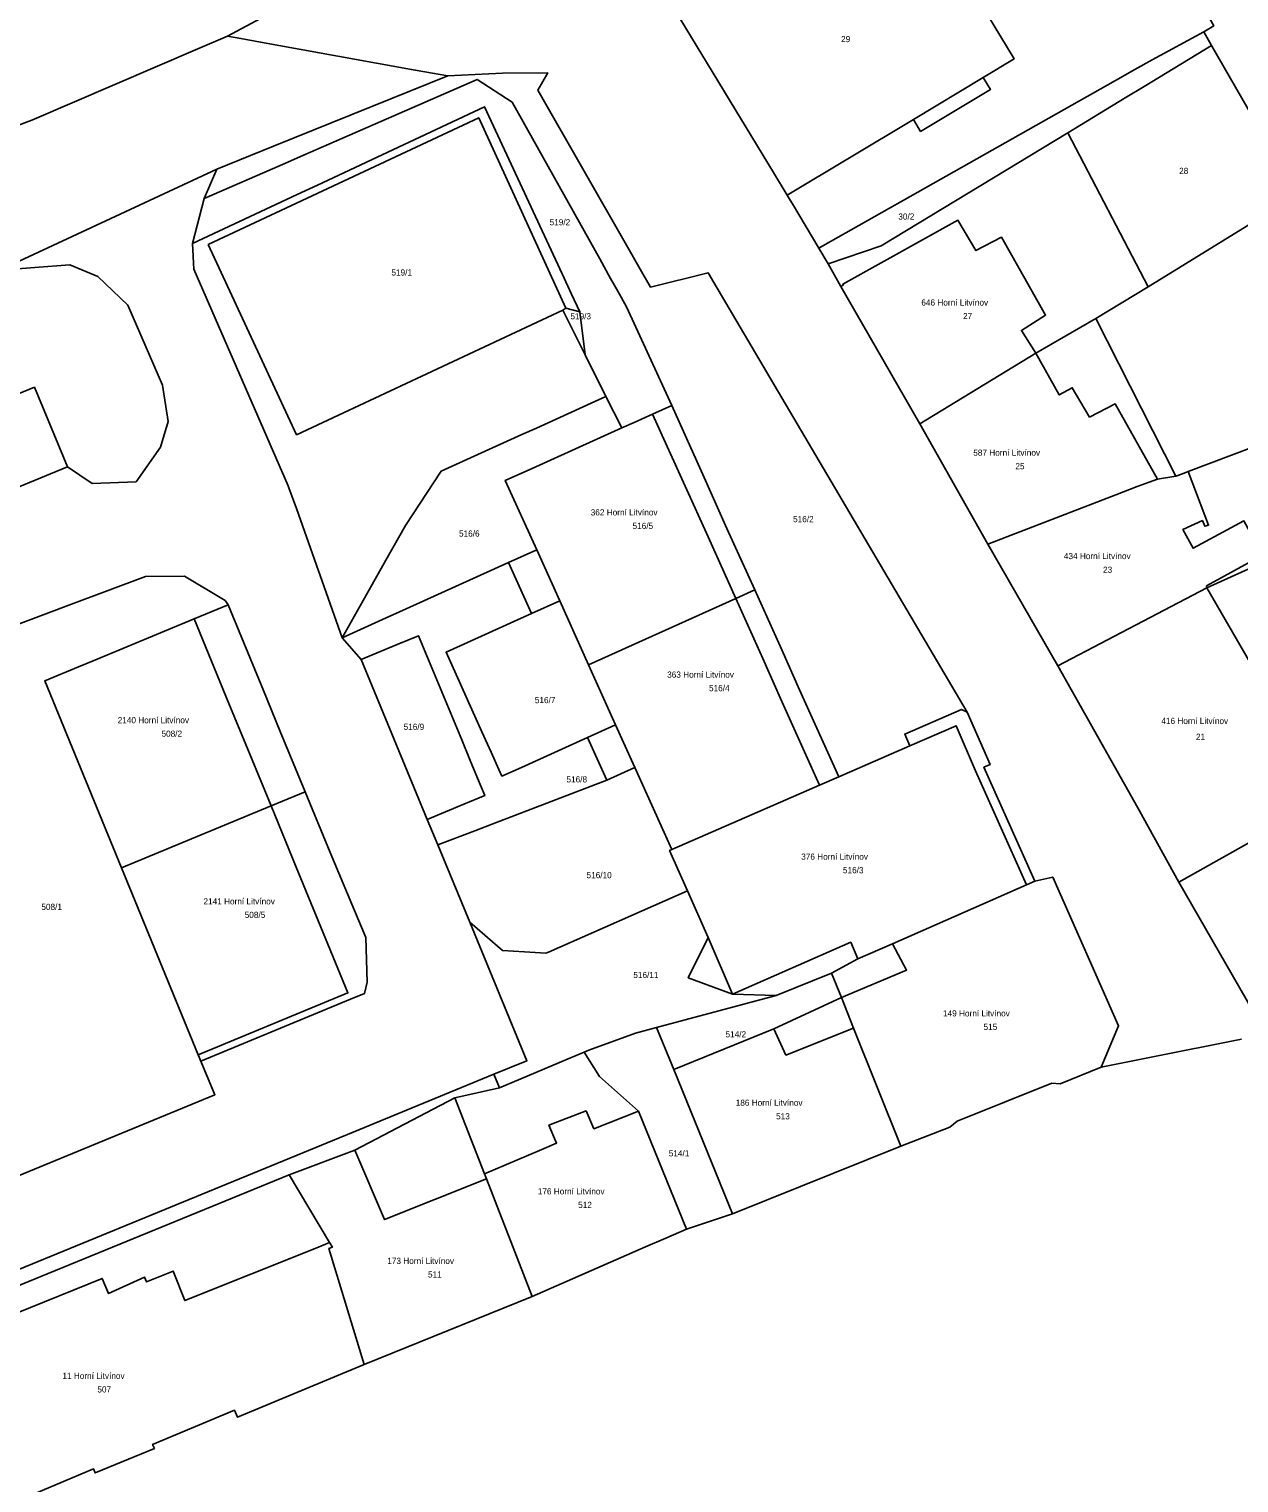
# Model space of a CAD drawing. Extents: x -792094 to -791524, y -979074 to -977761.
# Drawn here: x -791795.7 to -791697.5, y -978554.8 to -978436.7 of the extents above; entities that cross this region are included whole.
import ezdxf

# ---------------------------------------------------------------- set-up
doc = ezdxf.new("R2010")
doc.units = 0
doc.layers.add('katastr', color=7, linetype='Continuous')

msp = doc.modelspace()

# ---------------------------------------------------------------- linework, layer by layer
at = {"layer": 'katastr'}
for points in [[(-791639.24, -978372.34), (-791665.73, -978384.71), (-791679.28, -978391.82), (-791713.44, -978413.95), (-791712.96, -978414.79), (-791712, -978414.2), (-791699.5, -978436.46), (-791700.32, -978436.96), (-791699.69, -978438.07), (-791692.7, -978450.2), (-791683.8, -978465.99), (-791679.66, -978473.05), (-791670.22, -978489.33), (-791668.76, -978491.84), (-791668.28, -978492.67), (-791665.46, -978492.66), (-791655.51, -978492.64), (-791656.09, -978490.59), (-791634.23, -978485.99)], [(-791774.26, -978434.43), (-791779.62, -978437.31), (-791778.55, -978437.5), (-791776.94, -978437.79), (-791764.37, -978440.06), (-791761.73, -978440.54), (-791757.3, -978440.3), (-791753.61, -978440.27), (-791754.43, -978441.69), (-791747.1, -978454.48), (-791746.2, -978456.05), (-791745.26, -978457.69), (-791740.59, -978456.52), (-791740.13, -978457.31), (-791719.53, -978492.23), (-791717.68, -978496.48), (-791718.18, -978496.7), (-791714.04, -978505.95), (-791712.59, -978505.62), (-791707.23, -978517.71), (-791708.64, -978521.07), (-791704.72, -978520.29), (-791697.24, -978518.8)], [(-791695.21, -978518.4), (-791702.33, -978506.02), (-791705.66, -978500), (-791712.17, -978488.46), (-791717.87, -978478.58), (-791723.37, -978468.8), (-791729.8, -978457.63), (-791730.83, -978455.79), (-791731.58, -978454.53), (-791733.73, -978450.92), (-791733.91, -978450.62), (-791734.16, -978450.22), (-791735.27, -978448.37), (-791743.77, -978434.34)], [(-791798.15, -978456.32), (-791780.49, -978448.1), (-791775.89, -978446.25), (-791774.21, -978445.57), (-791761.73, -978440.54), (-791764.37, -978440.06), (-791776.94, -978437.79), (-791778.55, -978437.5), (-791779.62, -978437.31), (-791782.04, -978438.34), (-791795.52, -978444.13), (-791797.38, -978444.82)], [(-791819.57, -978546.91), (-791769.41, -978526.33), (-791757.99, -978521.62), (-791755.3, -978520.54), (-791759.94, -978509.29), (-791762.54, -978503.01), (-791763.4, -978500.93), (-791768.76, -978487.94), (-791770.31, -978486.17), (-791774.03, -978475.68), (-791774.64, -978473.99), (-791774.69, -978473.84), (-791782.37, -978456.24), (-791782.47, -978454.15), (-791781.53, -978450.5), (-791780.49, -978448.1), (-791798.15, -978456.32), (-791792.44, -978455.89), (-791790.15, -978456.83), (-791787.73, -978459.17), (-791784.9, -978465.65), (-791784.46, -978468.6), (-791785.07, -978470.7), (-791787.06, -978473.52), (-791790.63, -978473.64), (-791792.64, -978472.3), (-791843.49, -978493.26)], [(-791796.68, -978529.91), (-791780.67, -978523.32), (-791781.8, -978520.57), (-791782.01, -978520.06), (-791788.24, -978504.87), (-791794.47, -978489.67), (-791791.72, -978488.53), (-791790.53, -978488.04), (-791782.34, -978484.64), (-791779.57, -978483.49), (-791779.82, -978483.14), (-791783.13, -978481.18), (-791786.28, -978481.2), (-791792.51, -978483.54), (-791797.47, -978485.4)], [(-791797.47, -978485.4), (-791792.51, -978483.54), (-791786.28, -978481.2), (-791783.13, -978481.18), (-791779.82, -978483.14), (-791779.57, -978483.49), (-791776.71, -978490.45), (-791775.34, -978493.78), (-791773.32, -978498.69), (-791771.28, -978503.63), (-791769.89, -978506.97), (-791768.39, -978510.54), (-791768.28, -978514.16), (-791768.49, -978515.07), (-791769.63, -978515.54), (-791781.8, -978520.57), (-791780.67, -978523.32), (-791796.68, -978529.91)], [(-791697.24, -978518.8), (-791704.72, -978520.29), (-791708.64, -978521.07), (-791711.99, -978522.42), (-791712.65, -978522.37), (-791720.34, -978525.46), (-791720.94, -978525.94), (-791724.92, -978527.48), (-791738.59, -978532.97), (-791742.35, -978534.22), (-791744.02, -978534.95), (-791745.67, -978535.67), (-791754.88, -978539.7), (-791768.52, -978545.22), (-791778.82, -978549.5), (-791779.05, -978548.94), (-791785.71, -978551.71), (-791785.57, -978552.04), (-791790.37, -978554.03), (-791790.51, -978553.7), (-791797.13, -978556.47)], [(-791811.43, -978544.86), (-791774.63, -978529.81), (-791769.28, -978527.8), (-791761.16, -978523.56), (-791757.54, -978522.74), (-791757.99, -978521.62), (-791769.41, -978526.33), (-791819.57, -978546.91)], [(-791797.13, -978556.47), (-791790.51, -978553.7), (-791790.37, -978554.03), (-791785.57, -978552.04), (-791785.71, -978551.71), (-791779.05, -978548.94), (-791778.82, -978549.5), (-791768.52, -978545.22), (-791771.39, -978535.79), (-791771.11, -978535.68), (-791771.33, -978535.31), (-791772.36, -978535.73), (-791783.1, -978540.03), (-791784.04, -978537.63), (-791786.21, -978538.51), (-791786.37, -978538.11), (-791789.29, -978539.46), (-791789.81, -978538.22), (-791796.77, -978541.06)]]:
    msp.add_lwpolyline(points, dxfattribs=at)
for points in [[(-791800.48, -978414.05), (-791800.29, -978417.39), (-791800.13, -978420.23), (-791799.16, -978437.14), (-791798.94, -978441.72), (-791798.74, -978445.45), (-791797.38, -978444.82), (-791795.52, -978444.13), (-791782.04, -978438.34), (-791779.62, -978437.31), (-791774.26, -978434.43), (-791773.12, -978431.78), (-791776.62, -978427.28), (-791778.16, -978426.44), (-791786.66, -978421.71), (-791796.41, -978416.2), (-791798.26, -978415.26)], [(-791731.58, -978454.53), (-791731.27, -978454.35), (-791707.49, -978440.91), (-791705.92, -978440.02), (-791704.52, -978439.23), (-791700.32, -978436.96), (-791699.5, -978436.46), (-791712, -978414.2), (-791712.96, -978414.79), (-791717.16, -978417.4), (-791732.42, -978426.87), (-791744.02, -978433.92), (-791743.77, -978434.34), (-791725.3, -978423.3), (-791715.73, -978439.15), (-791718.24, -978440.67), (-791717.65, -978441.64), (-791723.32, -978445.04), (-791723.9, -978444.08), (-791734.16, -978450.22), (-791733.91, -978450.62), (-791733.73, -978450.92)], [(-791723.9, -978444.08), (-791718.24, -978440.67), (-791715.73, -978439.15), (-791725.3, -978423.3), (-791743.77, -978434.34), (-791735.27, -978448.37), (-791734.16, -978450.22)], [(-791715.73, -978439.15), (-791725.3, -978423.3), (-791743.77, -978434.34), (-791735.27, -978448.37), (-791734.16, -978450.22), (-791723.9, -978444.08), (-791723.32, -978445.04), (-791717.65, -978441.64), (-791718.24, -978440.67)], [(-791711.35, -978445.15), (-791706.69, -978442.32), (-791705.15, -978441.38), (-791699.69, -978438.07), (-791700.32, -978436.96), (-791704.52, -978439.23), (-791705.92, -978440.02), (-791707.49, -978440.91), (-791731.27, -978454.35), (-791731.58, -978454.53), (-791730.83, -978455.79), (-791726.52, -978454.35)], [(-791704.84, -978457.66), (-791692.7, -978450.2), (-791699.69, -978438.07), (-791705.15, -978441.38), (-791706.69, -978442.32), (-791711.35, -978445.15)], [(-791751, -978459.7), (-791750.57, -978463.19), (-791748.88, -978466.58), (-791747.6, -978469.13), (-791746.6, -978468.68), (-791745.09, -978468), (-791743.54, -978467.3), (-791747.21, -978459.28), (-791747.91, -978458.03), (-791748.5, -978456.98), (-791749.38, -978455.39), (-791756.49, -978442.66), (-791759.34, -978440.82), (-791773.51, -978447), (-791775.16, -978447.72), (-791781.53, -978450.5), (-791782.47, -978454.15), (-791773.96, -978450.17), (-791772.33, -978449.4), (-791758.74, -978443.04), (-791752.43, -978456.62), (-791751.67, -978458.26)], [(-791754.43, -978441.69), (-791753.61, -978440.27), (-791757.3, -978440.3), (-791761.73, -978440.54), (-791774.21, -978445.57), (-791775.89, -978446.25), (-791780.49, -978448.1), (-791781.53, -978450.5), (-791775.16, -978447.72), (-791773.51, -978447), (-791759.34, -978440.82), (-791756.49, -978442.66), (-791749.38, -978455.39), (-791748.5, -978456.98), (-791747.91, -978458.03), (-791747.21, -978459.28), (-791743.54, -978467.3), (-791740.91, -978473.16), (-791739.05, -978477.3), (-791736.78, -978482.29), (-791734.6, -978487.17), (-791733.15, -978490.4), (-791729.96, -978497.47), (-791724.19, -978494.96), (-791724.61, -978494), (-791719.99, -978492), (-791719.53, -978492.23), (-791740.13, -978457.31), (-791740.59, -978456.52), (-791745.26, -978457.69), (-791746.2, -978456.05), (-791747.1, -978454.48)], [(-791782.47, -978454.15), (-791782.37, -978456.24), (-791774.69, -978473.84), (-791774.64, -978473.99), (-791774.03, -978475.68), (-791770.31, -978486.17), (-791767.88, -978481.86), (-791766.76, -978479.87), (-791765.17, -978477.06), (-791762.28, -978472.64), (-791755.71, -978469.67), (-791754.53, -978469.14), (-791750.09, -978467.13), (-791748.88, -978466.58), (-791750.57, -978463.19), (-791752.39, -978459.56), (-791752.14, -978459.41), (-791751, -978459.7), (-791751.67, -978458.26), (-791752.43, -978456.62), (-791758.74, -978443.04), (-791772.33, -978449.4), (-791773.96, -978450.17)], [(-791781.21, -978454.23), (-791774.01, -978469.68), (-791752.39, -978459.56), (-791752.14, -978459.41), (-791759.21, -978443.93)], [(-791704.84, -978457.66), (-791711.35, -978445.15), (-791726.52, -978454.35), (-791730.83, -978455.79), (-791729.8, -978457.63), (-791723.37, -978468.8), (-791713.97, -978463.05), (-791709.08, -978460.25)], [(-791692.67, -978469.32), (-791683.8, -978465.99), (-791692.7, -978450.2), (-791704.84, -978457.66), (-791709.08, -978460.25), (-791702.58, -978473.05), (-791702.04, -978472.85), (-791701.59, -978472.66)], [(-791729.8, -978457.63), (-791723.37, -978468.8), (-791713.97, -978463.05), (-791715.13, -978461.21), (-791713.16, -978459.96), (-791716.76, -978453.62), (-791718.82, -978454.72), (-791720.29, -978452.26), (-791729.63, -978457.45), (-791729.6, -978457.53)], [(-791852.16, -978500.54), (-791841.16, -978498.91), (-791843.49, -978493.26), (-791846.16, -978486.79), (-791795.31, -978465.83), (-791792.64, -978472.3), (-791790.63, -978473.64), (-791787.06, -978473.52), (-791785.07, -978470.7), (-791784.46, -978468.6), (-791784.9, -978465.65), (-791787.73, -978459.17), (-791790.15, -978456.83), (-791792.44, -978455.89), (-791798.15, -978456.32), (-791799.08, -978456.73), (-791857.93, -978482.79), (-791858.41, -978481.73), (-791859.55, -978479.21), (-791861.86, -978480.18)], [(-791750.57, -978463.19), (-791751, -978459.7), (-791752.14, -978459.41), (-791752.39, -978459.56)], [(-791723.37, -978468.8), (-791717.87, -978478.58), (-791707.45, -978474.56), (-791705.72, -978473.89), (-791704.08, -978473.28), (-791702.58, -978473.05), (-791709.08, -978460.25), (-791713.97, -978463.05)], [(-791723.37, -978468.8), (-791717.87, -978478.58), (-791707.45, -978474.56), (-791705.72, -978473.89), (-791704.08, -978473.28), (-791707.51, -978467.18), (-791709.59, -978468.25), (-791711, -978465.86), (-791712.06, -978466.45), (-791713.97, -978463.05)], [(-791756.79, -978480.06), (-791754.51, -978479.04), (-791757.06, -978473.4), (-791754.57, -978472.28), (-791753.39, -978471.74), (-791747.6, -978469.13), (-791748.88, -978466.58), (-791750.09, -978467.13), (-791754.53, -978469.14), (-791755.71, -978469.67), (-791762.28, -978472.64), (-791765.17, -978477.06), (-791766.76, -978479.87), (-791767.88, -978481.86), (-791770.31, -978486.17), (-791766.75, -978484.56), (-791765.11, -978483.82)], [(-791754.92, -978484.21), (-791752.64, -978483.18), (-791750.29, -978488.39), (-791738.33, -978482.99), (-791736.78, -978482.29), (-791739.05, -978477.3), (-791740.91, -978473.16), (-791743.54, -978467.3), (-791745.09, -978468), (-791746.6, -978468.68), (-791747.6, -978469.13), (-791753.39, -978471.74), (-791754.57, -978472.28), (-791757.06, -978473.4), (-791754.51, -978479.04), (-791756.79, -978480.06)], [(-791745.09, -978468), (-791746.6, -978468.68), (-791747.6, -978469.13), (-791753.39, -978471.74), (-791754.57, -978472.28), (-791757.06, -978473.4), (-791754.51, -978479.04), (-791752.64, -978483.18), (-791750.29, -978488.39), (-791738.33, -978482.99), (-791740.59, -978477.99), (-791742.46, -978473.85)], [(-791704.08, -978473.28), (-791705.72, -978473.89), (-791707.45, -978474.56), (-791717.87, -978478.58), (-791712.17, -978488.46), (-791700.06, -978482.13), (-791690.47, -978477.8), (-791689.99, -978477.58), (-791688.64, -978476.97), (-791690.81, -978473.51), (-791691.65, -978472.15), (-791692.67, -978469.32), (-791701.59, -978472.66), (-791702.04, -978472.85), (-791702.58, -978473.05)], [(-791717.87, -978478.58), (-791712.17, -978488.46), (-791700.06, -978482.13), (-791700.1, -978481.97), (-791695.54, -978479.47), (-791697.06, -978476.68), (-791701.18, -978478.9), (-791702.01, -978477.39), (-791700.43, -978476.66), (-791700.22, -978477.12), (-791699.93, -978477.04), (-791701.59, -978472.66), (-791702.04, -978472.85), (-791702.58, -978473.05), (-791704.08, -978473.28), (-791705.72, -978473.89), (-791707.45, -978474.56)], [(-791705.66, -978500), (-791702.33, -978506.02), (-791691.58, -978500), (-791689.96, -978499.12), (-791683.28, -978495.52), (-791683.09, -978495.42), (-791680.78, -978494.33), (-791690.47, -978477.8), (-791700.06, -978482.13), (-791712.17, -978488.46)], [(-791770.31, -978486.17), (-791768.76, -978487.94), (-791765.84, -978486.73), (-791764.1, -978486.01), (-791760.6, -978494.48), (-791759.91, -978496.15), (-791759.31, -978497.59), (-791758.73, -978499), (-791760.42, -978499.7), (-791763.4, -978500.93), (-791762.54, -978503.01), (-791759.53, -978501.86), (-791757.85, -978501.21), (-791748.81, -978497.75), (-791750.37, -978494.28), (-791755.75, -978496.71), (-791757.33, -978497.42), (-791757.58, -978496.87), (-791758.21, -978495.46), (-791758.96, -978493.81), (-791761.87, -978487.35), (-791754.92, -978484.21), (-791756.79, -978480.06), (-791765.11, -978483.82), (-791766.75, -978484.56)], [(-791736.78, -978482.29), (-791738.33, -978482.99), (-791750.29, -978488.39), (-791748.1, -978493.25), (-791750.37, -978494.28), (-791748.81, -978497.75), (-791746.53, -978496.71), (-791743.53, -978503.37), (-791731.52, -978498.15), (-791729.96, -978497.47), (-791733.15, -978490.4), (-791734.6, -978487.17)], [(-791712.17, -978488.46), (-791705.66, -978500), (-791702.33, -978506.02), (-791691.58, -978500), (-791689.96, -978499.12), (-791693.19, -978494.23), (-791692.11, -978493.64), (-791694.41, -978489.79), (-791695.3, -978490.34), (-791700.06, -978482.13)], [(-791773.32, -978498.69), (-791775.34, -978493.78), (-791776.71, -978490.45), (-791779.57, -978483.49), (-791782.34, -978484.64), (-791790.53, -978488.04), (-791791.72, -978488.53), (-791794.47, -978489.67), (-791788.24, -978504.87), (-791776.09, -978499.83)], [(-791750.37, -978494.28), (-791748.1, -978493.25), (-791750.29, -978488.39), (-791752.64, -978483.18), (-791754.92, -978484.21), (-791761.87, -978487.35), (-791758.96, -978493.81), (-791758.21, -978495.46), (-791757.58, -978496.87), (-791757.33, -978497.42), (-791755.75, -978496.71)], [(-791738.33, -978482.99), (-791750.29, -978488.39), (-791748.1, -978493.25), (-791746.53, -978496.71), (-791743.53, -978503.37), (-791731.52, -978498.15), (-791734.69, -978491.1), (-791736.15, -978487.87)], [(-791778.14, -978494.86), (-791779.52, -978491.51), (-791782.34, -978484.64), (-791790.53, -978488.04), (-791791.72, -978488.53), (-791794.47, -978489.67), (-791788.24, -978504.87), (-791776.09, -978499.83)], [(-791763.4, -978500.93), (-791760.42, -978499.7), (-791758.73, -978499), (-791759.31, -978497.59), (-791759.91, -978496.15), (-791760.6, -978494.48), (-791764.1, -978486.01), (-791765.84, -978486.73), (-791768.76, -978487.94)], [(-791731.52, -978498.15), (-791743.53, -978503.37), (-791743.71, -978503.45), (-791742.26, -978506.73), (-791740.59, -978510.52), (-791742.19, -978513.8), (-791738.61, -978515.12), (-791735.05, -978515.23), (-791730.55, -978513.43), (-791728.43, -978512.27), (-791725.61, -978511.04), (-791714.72, -978506.26), (-791714.04, -978505.95), (-791718.18, -978496.7), (-791717.68, -978496.48), (-791719.53, -978492.23), (-791719.99, -978492), (-791724.61, -978494), (-791724.19, -978494.96), (-791729.96, -978497.47)], [(-791740.59, -978510.52), (-791738.61, -978515.12), (-791729, -978510.92), (-791728.43, -978512.27), (-791725.61, -978511.04), (-791714.72, -978506.26), (-791718.87, -978497), (-791720.43, -978493.33), (-791724.19, -978494.96), (-791729.96, -978497.47), (-791731.52, -978498.15), (-791743.53, -978503.37), (-791743.71, -978503.45), (-791742.26, -978506.73)], [(-791695.21, -978518.4), (-791682.9, -978511.6), (-791676.17, -978508.15), (-791680.86, -978500), (-791683.28, -978495.52), (-791689.96, -978499.12), (-791691.58, -978500), (-791702.33, -978506.02)], [(-791759.94, -978509.29), (-791757.28, -978511.58), (-791755.5, -978511.7), (-791753.78, -978511.81), (-791753.55, -978511.71), (-791742.26, -978506.73), (-791743.71, -978503.45), (-791743.53, -978503.37), (-791746.53, -978496.71), (-791748.81, -978497.75), (-791757.85, -978501.21), (-791759.53, -978501.86), (-791762.54, -978503.01)], [(-791769.89, -978506.97), (-791771.28, -978503.63), (-791773.32, -978498.69), (-791776.09, -978499.83), (-791788.24, -978504.87), (-791782.01, -978520.06), (-791781.8, -978520.57), (-791769.63, -978515.54), (-791768.49, -978515.07), (-791768.28, -978514.16), (-791768.39, -978510.54)], [(-791782.01, -978520.06), (-791769.84, -978515.03), (-791772.66, -978508.18), (-791774.04, -978504.82), (-791776.09, -978499.83), (-791788.24, -978504.87)], [(-791702.33, -978506.02), (-791695.21, -978518.4), (-791682.9, -978511.6), (-791685.15, -978507.64), (-791683.48, -978506.74), (-791686.11, -978502.21), (-791688.06, -978503.2), (-791689.96, -978499.12), (-791691.58, -978500)], [(-791725.61, -978511.04), (-791728.43, -978512.27), (-791730.55, -978513.43), (-791729.74, -978515.4), (-791728.77, -978517.88), (-791724.92, -978527.48), (-791720.94, -978525.94), (-791720.34, -978525.46), (-791712.65, -978522.37), (-791711.99, -978522.42), (-791708.64, -978521.07), (-791707.23, -978517.71), (-791712.59, -978505.62), (-791714.04, -978505.95), (-791714.72, -978506.26)], [(-791728.77, -978517.88), (-791724.92, -978527.48), (-791720.94, -978525.94), (-791720.34, -978525.46), (-791712.65, -978522.37), (-791711.99, -978522.42), (-791708.64, -978521.07), (-791707.23, -978517.71), (-791712.59, -978505.62), (-791714.04, -978505.95), (-791714.72, -978506.26), (-791725.61, -978511.04), (-791724.46, -978513.18), (-791729.74, -978515.4)], [(-791744.78, -978517.83), (-791735.05, -978515.23), (-791738.61, -978515.12), (-791742.19, -978513.8), (-791740.59, -978510.52), (-791742.26, -978506.73), (-791753.55, -978511.71), (-791753.78, -978511.81), (-791755.5, -978511.7), (-791757.28, -978511.58), (-791759.94, -978509.29), (-791755.3, -978520.54), (-791757.99, -978521.62), (-791757.54, -978522.74), (-791756.49, -978522.3), (-791751.94, -978520.38), (-791750.64, -978519.83), (-791750.27, -978519.69), (-791746.49, -978518.29)], [(-791730.55, -978513.43), (-791735.05, -978515.23), (-791744.78, -978517.83), (-791743.38, -978521.26), (-791735.23, -978517.95), (-791729.74, -978515.4)], [(-791728.77, -978517.88), (-791729.74, -978515.4), (-791735.23, -978517.95), (-791743.38, -978521.26), (-791738.59, -978532.97), (-791724.92, -978527.48)], [(-791746.23, -978524.63), (-791742.35, -978534.22), (-791738.59, -978532.97), (-791743.38, -978521.26), (-791744.78, -978517.83), (-791746.49, -978518.29), (-791750.27, -978519.69), (-791750.64, -978519.83), (-791749.41, -978521.83)], [(-791735.23, -978517.95), (-791743.38, -978521.26), (-791738.59, -978532.97), (-791724.92, -978527.48), (-791728.77, -978517.88), (-791734.26, -978520.08)], [(-791742.35, -978534.22), (-791746.23, -978524.63), (-791749.41, -978521.83), (-791750.64, -978519.83), (-791751.94, -978520.38), (-791756.49, -978522.3), (-791757.54, -978522.74), (-791761.16, -978523.56), (-791758.76, -978529.74), (-791758.6, -978530.14), (-791754.88, -978539.7), (-791745.67, -978535.67), (-791744.02, -978534.95)], [(-791758.6, -978530.14), (-791758.76, -978529.74), (-791761.16, -978523.56), (-791769.28, -978527.8), (-791774.63, -978529.81), (-791771.33, -978535.31), (-791771.11, -978535.68), (-791771.39, -978535.79), (-791768.52, -978545.22), (-791754.88, -978539.7)], [(-791746.23, -978524.63), (-791749.86, -978526.06), (-791750.49, -978524.62), (-791753.52, -978525.77), (-791752.89, -978527.23), (-791754.29, -978527.83), (-791758.76, -978529.74), (-791758.6, -978530.14), (-791754.88, -978539.7), (-791745.67, -978535.67), (-791744.02, -978534.95), (-791742.35, -978534.22)], [(-791769.28, -978527.8), (-791774.63, -978529.81), (-791771.33, -978535.31), (-791771.11, -978535.68), (-791771.39, -978535.79), (-791768.52, -978545.22), (-791754.88, -978539.7), (-791758.6, -978530.14), (-791766.87, -978533.45)], [(-791771.33, -978535.31), (-791774.63, -978529.81), (-791811.43, -978544.86), (-791813.62, -978545.56), (-791812.93, -978547.11), (-791811.16, -978551.87), (-791807.29, -978561.32), (-791796.91, -978557.01), (-791797.13, -978556.47), (-791790.51, -978553.7), (-791790.37, -978554.03), (-791785.57, -978552.04), (-791785.71, -978551.71), (-791779.05, -978548.94), (-791778.82, -978549.5), (-791768.52, -978545.22), (-791771.39, -978535.79), (-791771.11, -978535.68)]]:
    msp.add_lwpolyline(points, close=True, dxfattribs=at)

# ---------------------------------------------------------------- texts
for s, p in [('29', (-791729.78, -978437.79)), ('28', (-791702.32, -978448.5)), ('30/2', (-791725.13, -978452.21)), ('519/2', (-791753.46, -978452.67)), ('519/1', (-791766.31, -978456.75)), ('646 Horní Litvínov', (-791723.26, -978459.19)), ('519/3', (-791751.77, -978460.31)), ('27', (-791719.87, -978460.29)), ('587 Horní Litvínov', (-791719.04, -978471.39)), ('25', (-791715.62, -978472.49)), ('362 Horní Litvínov', (-791750.12, -978476.24)), ('516/2', (-791733.68, -978476.79)), ('516/6', (-791760.82, -978477.96)), ('516/5', (-791746.72, -978477.34)), ('434 Horní Litvínov', (-791711.68, -978479.79)), ('23', (-791708.5, -978480.9)), ('363 Horní Litvínov', (-791743.91, -978489.42)), ('516/4', (-791740.51, -978490.52)), ('516/7', (-791754.66, -978491.49)), ('2140 Horní Litvínov', (-791788.55, -978493.12)), ('516/9', (-791765.32, -978493.66)), ('416 Horní Litvínov', (-791703.76, -978493.18)), ('508/2', (-791784.99, -978494.22)), ('21', (-791700.95, -978494.47)), ('516/8', (-791752.09, -978497.93)), ('376 Horní Litvínov', (-791733.02, -978504.21)), ('516/3', (-791729.63, -978505.31)), ('516/10', (-791750.46, -978505.71)), ('2141 Horní Litvínov', (-791781.58, -978507.84)), ('508/1', (-791794.75, -978508.29)), ('508/5', (-791778.23, -978508.94)), ('516/11', (-791746.66, -978513.82)), ('149 Horní Litvínov', (-791721.5, -978516.94)), ('515', (-791718.21, -978518.04)), ('514/2', (-791739.17, -978518.64)), ('186 Horní Litvínov', (-791738.34, -978524.2)), ('513', (-791735.06, -978525.3)), ('514/1', (-791743.78, -978528.31)), ('176 Horní Litvínov', (-791754.42, -978531.4)), ('512', (-791751.14, -978532.5)), ('173 Horní Litvínov', (-791766.65, -978537.05)), ('511', (-791763.34, -978538.15)), ('11 Horní Litvínov', (-791793.04, -978546.39)), ('507', (-791790.2, -978547.49))]:
    msp.add_text(s, height=0.5, dxfattribs=at).set_placement(p)

doc.saveas('drawing.dxf')
